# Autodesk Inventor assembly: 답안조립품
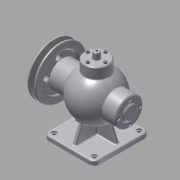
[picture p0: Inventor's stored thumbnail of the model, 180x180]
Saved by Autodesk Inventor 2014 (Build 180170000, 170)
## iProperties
Created: 2015-10
Part Number: 답안조립품
Document SubType Name: Assembly
Designer: youjin05
Author: youjin05
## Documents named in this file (19)
- C:\Users\youjin05\Desktop\451010V1012\답안조립품.iam
- C:\Users\youjin05\Desktop\451010V1012\본체.ipt
- C:\Users\youjin05\Desktop\451010V1012\뒤커버.ipt
- C:\Users\youjin05\Desktop\451010V1012\앞커버.ipt
- C:\Users\youjin05\Desktop\451010V1012\상부커버.ipt
- C:\Users\youjin05\Desktop\451010V1012\베어링- 6202.ipt
- KS B 2023 - 6202 - 15 x 35 x 11 - 7.8.ipt
- C:\Users\youjin05\Desktop\451010V1012\오일실 15 30 7.ipt
- C:\Users\youjin05\Desktop\451010V1012\멈춤링- 15 x 1.ipt
- C:\Users\youjin05\Desktop\451010V1012\멈춤링- 35x1.6.ipt
- KS B 1336 - 35x1.6.ipt
- C:\Users\youjin05\Desktop\451010V1012\부시.ipt
- C:\Users\youjin05\Desktop\451010V1012\편심축.ipt
- C:\Users\youjin05\Desktop\451010V1012\슬라이드.ipt
- C:\Users\youjin05\Desktop\451010V1012\볼트 M4 x 16.ipt
- C:\Users\youjin05\Desktop\451010V1012\볼트 M 4 x 12.ipt
- C:\Users\youjin05\Desktop\451010V1012\키 4 x 4 x 12.ipt
- C:\Users\youjin05\Desktop\451010V1012\V-벨트풀리.ipt
- C:\Users\youjin05\Desktop\451010V1012\너트 M8.ipt
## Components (16 placed, 5 different names)
1. KS B 2023 - 6202 - 15 x 35 x 11 - 7.8:1 — 각도:2
2. KS B 2023 - 6202 - 15 x 35 x 11 - 7.8:2 — 각도:1
3. KS B 1336 - 35x1.6:1
4. V-벨트풀리:1
5. ISO 4762 M4 x 16:2
6. ISO 4762 M4 x 16:3
7. ISO 4762 M4 x 16:4
8. ISO 4762 M4 x 16:5
9. ISO 4762 M4 x 16:1
10. ISO 4762 M4 x 16:6
11. ISO 4762 M4 x 16:7
12. ISO 4762 M4 x 16:8
13. KS B 1021 - 에 따름 ISO 1207 - 미터 A  M 4 x 12:1
14. KS B 1021 - 에 따름 ISO 1207 - 미터 A  M 4 x 12:2
15. KS B 1021 - 에 따름 ISO 1207 - 미터 A  M 4 x 12:3
16. KS B 1021 - 에 따름 ISO 1207 - 미터 A  M 4 x 12:4
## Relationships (2: Angle 2)
- 각도:1 [Angle]: KS B 2023 - 6202 - 15 x 35 x 11 - 7.8:2
- 각도:2 [Angle]: KS B 2023 - 6202 - 15 x 35 x 11 - 7.8:1
